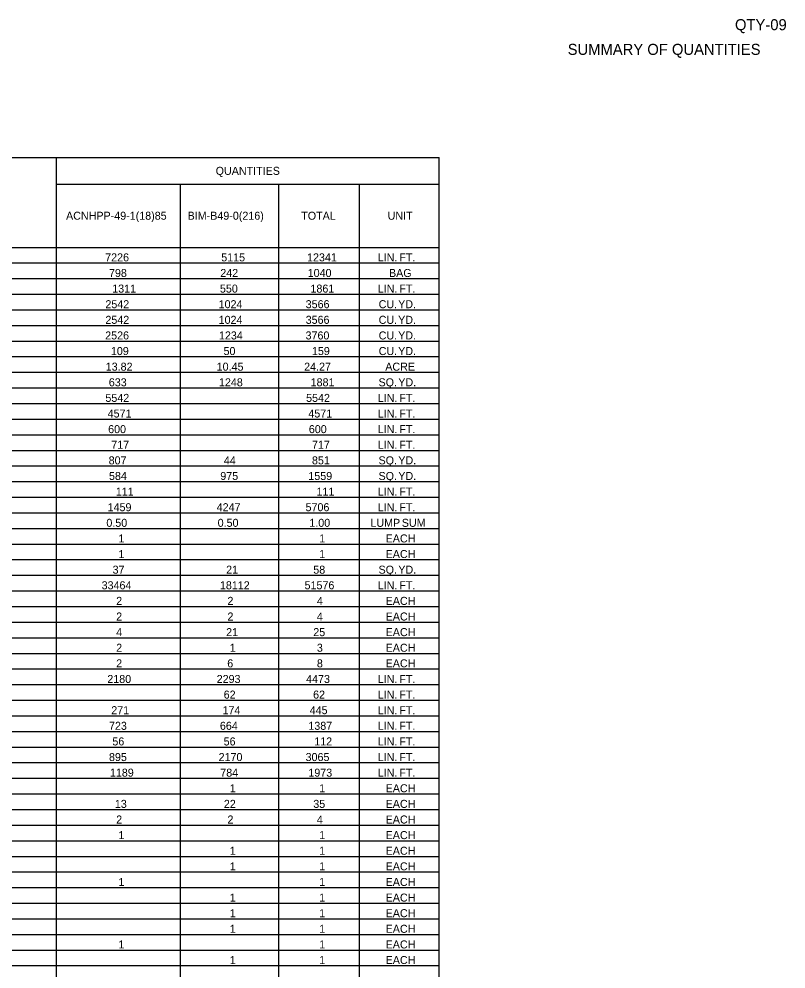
# Model space of a CAD drawing. Extents: x 1226603 to 1228117, y 151305 to 152343.
# Drawn here: x 1227702 to 1228109, y 151801 to 152305 of the extents above; entities that cross this region are included whole.
import ezdxf

# ---------------------------------------------------------------- set-up
doc = ezdxf.new("R2010")
doc.units = 0
doc.layers.add('R_Border', color=7, linetype='Continuous')
doc.layers.add('R_Dimension', color=7, linetype='Continuous')

msp = doc.modelspace()

# ---------------------------------------------------------------- linework, layer by layer
at = {"layer": 'R_Dimension'}
for p, q in [((1227295.33, 152231.95), (1227925.18, 152231.95)), ((1227722.14, 151330.69), (1227722.14, 152231.95)), ((1227925.18, 151330.69), (1227925.18, 152231.95)), ((1227722.14, 152217.86), (1227925.18, 152217.86)), ((1227788.02, 151330.69), (1227788.02, 152217.86)), ((1227840.23, 151330.69), (1227840.23, 152217.86)), ((1227882.92, 151330.69), (1227882.92, 152217.86)), ((1227295.33, 152184.3), (1227925.18, 152184.3)), ((1227295.33, 152176.01), (1227925.18, 152176.01)), ((1227295.33, 152167.73), (1227925.18, 152167.73)), ((1227295.33, 152159.44), (1227925.18, 152159.44)), ((1227295.33, 152151.15), (1227925.18, 152151.15)), ((1227295.33, 152142.86), (1227925.18, 152142.86)), ((1227295.33, 152134.58), (1227925.18, 152134.58)), ((1227295.33, 152126.29), (1227925.18, 152126.29)), ((1227295.33, 152118), (1227925.18, 152118)), ((1227295.33, 152109.71), (1227925.18, 152109.71)), ((1227295.33, 152101.43), (1227925.18, 152101.43)), ((1227295.33, 152093.14), (1227925.18, 152093.14)), ((1227295.33, 152084.85), (1227925.18, 152084.85)), ((1227295.33, 152076.56), (1227925.18, 152076.56)), ((1227295.33, 152068.28), (1227925.18, 152068.28)), ((1227295.33, 152059.99), (1227925.18, 152059.99)), ((1227295.33, 152051.7), (1227925.18, 152051.7)), ((1227295.33, 152043.41), (1227925.18, 152043.41)), ((1227295.33, 152035.13), (1227925.18, 152035.13)), ((1227295.33, 152026.84), (1227925.18, 152026.84)), ((1227295.33, 152018.55), (1227925.18, 152018.55)), ((1227295.33, 152010.26), (1227925.18, 152010.26)), ((1227295.33, 152001.98), (1227925.18, 152001.98)), ((1227295.33, 151993.69), (1227925.18, 151993.69)), ((1227295.33, 151985.4), (1227925.18, 151985.4)), ((1227295.33, 151977.11), (1227925.18, 151977.11)), ((1227295.33, 151968.83), (1227925.18, 151968.83)), ((1227295.33, 151960.54), (1227925.18, 151960.54)), ((1227295.33, 151952.25), (1227925.18, 151952.25)), ((1227295.33, 151943.96), (1227925.18, 151943.96)), ((1227295.33, 151935.68), (1227925.18, 151935.68)), ((1227295.33, 151927.39), (1227925.18, 151927.39)), ((1227295.33, 151919.1), (1227925.18, 151919.1)), ((1227295.33, 151910.81), (1227925.18, 151910.81)), ((1227295.33, 151902.53), (1227925.18, 151902.53)), ((1227295.33, 151894.24), (1227925.18, 151894.24)), ((1227295.33, 151885.95), (1227925.18, 151885.95)), ((1227295.33, 151877.66), (1227925.18, 151877.66)), ((1227295.33, 151869.38), (1227925.18, 151869.38)), ((1227295.33, 151861.09), (1227925.18, 151861.09)), ((1227295.33, 151852.8), (1227925.18, 151852.8)), ((1227295.33, 151844.51), (1227925.18, 151844.51)), ((1227295.33, 151836.23), (1227925.18, 151836.23)), ((1227295.33, 151827.94), (1227925.18, 151827.94)), ((1227295.33, 151819.65), (1227925.18, 151819.65)), ((1227295.33, 151811.36), (1227925.18, 151811.36)), ((1227295.33, 151803.08), (1227925.18, 151803.08))]:
    msp.add_line(p, q, dxfattribs=at)

# ---------------------------------------------------------------- texts
at = {"layer": 'R_Border'}
for s, height, p in [('QTY-09', 5.861, (1228082.22, 152299.55)), ('SUMMARY OF QUANTITIES', 5.862, (1227993.44, 152286.45))]:
    msp.add_text(s, height=height, dxfattribs=at).set_placement(p)
at = {"layer": 'R_Dimension'}
for s, p in [('QUANTITIES', (1227806.66, 152222.78)), ('ACNHPP-49-1(18)85', (1227727.27, 152198.96)), ('BIM-B49-0(216)', (1227791.78, 152198.96)), ('TOTAL', (1227852.07, 152198.96)), ('UNIT', (1227897.91, 152198.96)), ('7226', (1227748.04, 152176.86)), ('5115', (1227809.61, 152176.86)), ('12341', (1227855.15, 152176.86)), ('LIN.', (1227892.65, 152176.86)), (' FT.', (1227902.56, 152176.86)), ('798', (1227750.06, 152168.58)), ('242', (1227809.11, 152168.58)), ('1040', (1227855.5, 152168.58)), ('BAG', (1227898.64, 152168.58)), ('1311', (1227751.77, 152160.29)), ('550', (1227808.93, 152160.29)), ('1861', (1227856.96, 152160.29)), ('LIN.', (1227892.65, 152160.29)), (' FT.', (1227902.56, 152160.29)), ('2542', (1227748.15, 152152)), ('1024', (1227808.24, 152152)), ('3566', (1227854.43, 152152)), ('CU.', (1227893.16, 152152)), (' YD.', (1227901.92, 152152)), ('2542', (1227748.15, 152143.71)), ('1024', (1227808.24, 152143.71)), ('3566', (1227854.43, 152143.71)), ('CU.', (1227893.16, 152143.71)), (' YD.', (1227901.92, 152143.71)), ('2526', (1227748.04, 152135.43)), ('1234', (1227808.41, 152135.43)), ('3760', (1227854.36, 152135.43)), ('CU.', (1227893.16, 152135.43)), (' YD.', (1227901.92, 152135.43)), ('109', (1227751.08, 152127.14)), ('50', (1227810.83, 152127.14)), ('159', (1227857.74, 152127.14)), ('CU.', (1227893.16, 152127.14)), (' YD.', (1227901.92, 152127.14)), ('13.82', (1227748.32, 152118.85)), ('10.45', (1227807.2, 152118.85)), ('24.27', (1227853.61, 152118.85)), ('ACRE', (1227896.65, 152118.85)), ('633', (1227749.96, 152110.56)), ('1248', (1227808.41, 152110.56)), ('1881', (1227857.06, 152110.56)), ('SQ.', (1227893.09, 152110.56)), (' YD.', (1227901.99, 152110.56)), ('5542', (1227748.15, 152102.28)), ('5542', (1227854.65, 152102.28)), ('LIN.', (1227892.65, 152102.28)), (' FT.', (1227902.56, 152102.28)), ('4571', (1227749.36, 152093.99)), ('4571', (1227855.85, 152093.99)), ('LIN.', (1227892.65, 152093.99)), (' FT.', (1227902.56, 152093.99)), ('600', (1227749.61, 152085.7)), ('600', (1227856.1, 152085.7)), ('LIN.', (1227892.65, 152085.7)), (' FT.', (1227902.56, 152085.7)), ('717', (1227751.27, 152077.41)), ('717', (1227857.76, 152077.41)), ('LIN.', (1227892.65, 152077.41)), (' FT.', (1227902.56, 152077.41)), ('807', (1227749.89, 152069.13)), ('44', (1227811.02, 152069.13)), ('851', (1227857.76, 152069.13)), ('SQ.', (1227893.09, 152069.13)), (' YD.', (1227901.99, 152069.13)), ('584', (1227750.06, 152060.84)), ('975', (1227809.11, 152060.84)), ('1559', (1227855.84, 152060.84)), ('SQ.', (1227893.09, 152060.84)), (' YD.', (1227901.99, 152060.84)), ('111', (1227753.68, 152052.55)), ('111', (1227860.17, 152052.55)), ('LIN.', (1227892.65, 152052.55)), (' FT.', (1227902.56, 152052.55)), ('1459', (1227749.34, 152044.26)), ('4247', (1227807.2, 152044.26)), ('5706', (1227854.36, 152044.26)), ('LIN.', (1227892.65, 152044.26)), (' FT.', (1227902.56, 152044.26)), ('0.50', (1227748.67, 152035.98)), ('0.50', (1227807.72, 152035.98)), ('1.00', (1227856.37, 152035.98)), ('LUMP', (1227888.76, 152035.98)), (' SUM', (1227903.85, 152035.98)), ('1', (1227755.08, 152027.69)), ('1', (1227861.58, 152027.69)), ('EACH', (1227896.85, 152027.69)), ('1', (1227755.08, 152019.4)), ('1', (1227861.58, 152019.4)), ('EACH', (1227896.85, 152019.4)), ('37', (1227751.97, 152011.11)), ('21', (1227812.22, 152011.11)), ('58', (1227858.46, 152011.11)), ('SQ.', (1227893.09, 152011.11)), (' YD.', (1227901.99, 152011.11)), ('33464', (1227746.15, 152002.83)), ('18112', (1227808.91, 152002.83)), ('51576', (1227853.83, 152002.83)), ('LIN.', (1227892.65, 152002.83)), (' FT.', (1227902.56, 152002.83)), ('2', (1227753.88, 151994.54)), ('2', (1227812.92, 151994.54)), ('4', (1227860.37, 151994.54)), ('EACH', (1227896.85, 151994.54)), ('2', (1227753.88, 151986.25)), ('2', (1227812.92, 151986.25)), ('4', (1227860.37, 151986.25)), ('EACH', (1227896.85, 151986.25)), ('4', (1227753.88, 151977.96)), ('21', (1227812.22, 151977.96)), ('25', (1227858.46, 151977.96)), ('EACH', (1227896.85, 151977.96)), ('2', (1227753.88, 151969.68)), ('1', (1227814.13, 151969.68)), ('3', (1227860.37, 151969.68)), ('EACH', (1227896.85, 151969.68)), ('2', (1227753.88, 151961.39)), ('6', (1227812.81, 151961.39)), ('8', (1227860.37, 151961.39)), ('EACH', (1227896.85, 151961.39)), ('2180', (1227749.17, 151953.1)), ('2293', (1227807.2, 151953.1)), ('4473', (1227854.65, 151953.1)), ('LIN.', (1227892.65, 151953.1)), (' FT.', (1227902.56, 151953.1)), ('62', (1227810.92, 151944.81)), ('62', (1227858.36, 151944.81)), ('LIN.', (1227892.65, 151944.81)), (' FT.', (1227902.56, 151944.81)), ('271', (1227751.27, 151936.53)), ('174', (1227810.31, 151936.53)), ('445', (1227856.56, 151936.53)), ('LIN.', (1227892.65, 151936.53)), (' FT.', (1227902.56, 151936.53)), ('723', (1227750.06, 151928.24)), ('664', (1227808.91, 151928.24)), ('1387', (1227855.85, 151928.24)), ('LIN.', (1227892.65, 151928.24)), (' FT.', (1227902.56, 151928.24)), ('56', (1227751.85, 151919.95)), ('56', (1227810.9, 151919.95)), ('112', (1227858.97, 151919.95)), ('LIN.', (1227892.65, 151919.95)), (' FT.', (1227902.56, 151919.95)), ('895', (1227750.06, 151911.66)), ('2170', (1227808.22, 151911.66)), ('3065', (1227854.38, 151911.66)), ('LIN.', (1227892.65, 151911.66)), (' FT.', (1227902.56, 151911.66)), ('1189', (1227750.55, 151903.38)), ('784', (1227809.11, 151903.38)), ('1973', (1227855.85, 151903.38)), ('LIN.', (1227892.65, 151903.38)), (' FT.', (1227902.56, 151903.38)), ('1', (1227814.13, 151895.09)), ('1', (1227861.58, 151895.09)), ('EACH', (1227896.85, 151895.09)), ('13', (1227753.17, 151886.8)), ('22', (1227811.02, 151886.8)), ('35', (1227858.46, 151886.8)), ('EACH', (1227896.85, 151886.8)), ('2', (1227753.88, 151878.51)), ('2', (1227812.92, 151878.51)), ('4', (1227860.37, 151878.51)), ('EACH', (1227896.85, 151878.51)), ('EACH', (1227896.85, 151870.23)), ('1', (1227755.08, 151870.23)), ('1', (1227861.58, 151870.23)), ('1', (1227814.13, 151861.94)), ('1', (1227861.58, 151861.94)), ('EACH', (1227896.85, 151861.94)), ('1', (1227814.13, 151853.65)), ('1', (1227861.58, 151853.65)), ('EACH', (1227896.85, 151853.65)), ('1', (1227755.08, 151845.36)), ('1', (1227861.58, 151845.36)), ('EACH', (1227896.85, 151845.36)), ('1', (1227814.13, 151837.08)), ('1', (1227861.58, 151837.08)), ('EACH', (1227896.85, 151837.08)), ('1', (1227814.13, 151828.79)), ('1', (1227861.58, 151828.79)), ('EACH', (1227896.85, 151828.79)), ('1', (1227814.13, 151820.5)), ('1', (1227861.58, 151820.5)), ('EACH', (1227896.85, 151820.5)), ('1', (1227755.08, 151812.21)), ('1', (1227861.58, 151812.21)), ('EACH', (1227896.85, 151812.21)), ('1', (1227814.13, 151803.93)), ('1', (1227861.58, 151803.93)), ('EACH', (1227896.85, 151803.93))]:
    msp.add_text(s, height=4.25, dxfattribs=at).set_placement(p)

doc.saveas('drawing.dxf')
